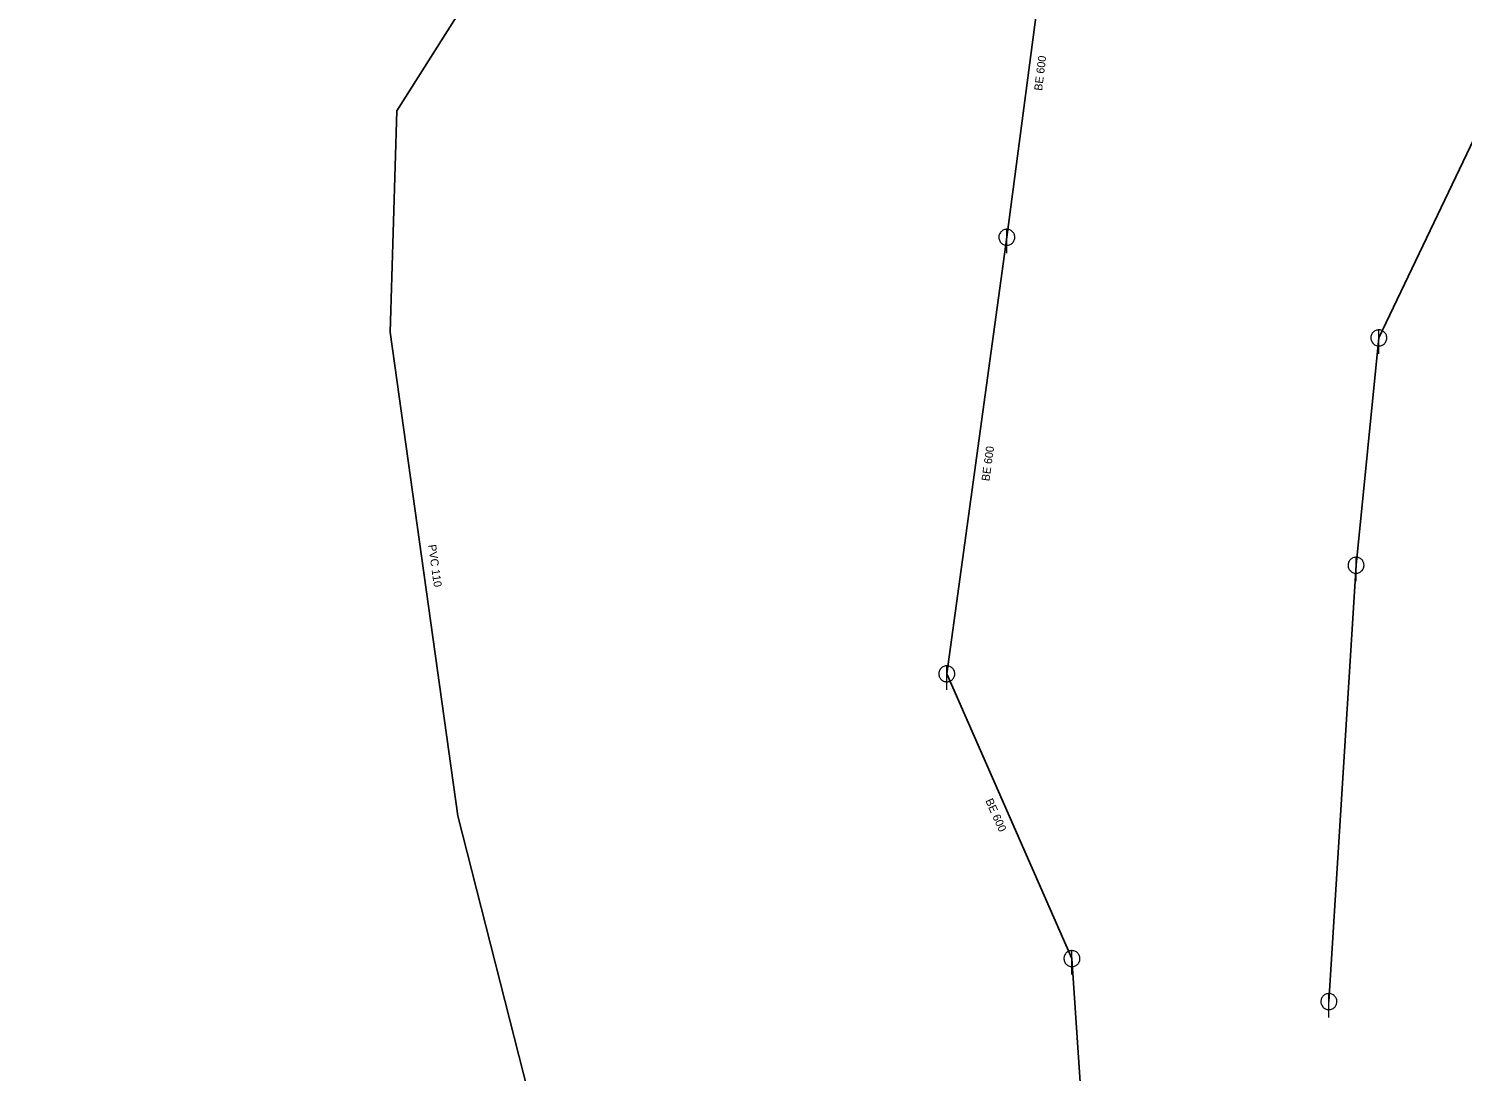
# Model space of a CAD drawing. Extents: x -659250 to -657316, y -997555 to -993684.
# Drawn here: x -658669.3 to -658490.2, y -994349.9 to -994219.6 of the extents above; entities that cross this region are included whole.
import ezdxf

# ---------------------------------------------------------------- set-up
doc = ezdxf.new("R2010")
doc.units = 0
doc.header["$LTSCALE"] = 0.4
doc.layers.add('1', color=7, linetype='Continuous')
for name, color, linetype, lineweight in [('14', 7, 'Continuous', 25), ('17', 7, 'Continuous', 25), ('22', 7, 'Continuous', 13)]:
    doc.layers.add(name, color=color, linetype=linetype, lineweight=lineweight)

msp = doc.modelspace()

# ---------------------------------------------------------------- linework, layer by layer
at = {"layer": '14'}
for p, q in [((-658547.12, -994245.69), (-658541.489, -994202.69)), ((-658506.89, -994341.18), (-658503.5, -994286.66))]:
    msp.add_line(p, q, dxfattribs=at)
for points in [[(-658503.5, -994286.66), (-658500.649, -994258.26), (-658488.28, -994232.379)], [(-658538.989, -994335.809), (-658554.62, -994300.23), (-658547.12, -994245.69)], [(-658665.989, -994692.25), (-658669.32, -994646.26), (-658665.8, -994630.84), (-658645.039, -994594.649), (-658628.309, -994572.48), (-658618.039, -994539.21), (-658605.98, -994522.41), (-658563.96, -994494.52), (-658544.98, -994467.27), (-658532.93, -994425.92), (-658538.989, -994335.809)]]:
    msp.add_lwpolyline(points, dxfattribs=at)
at = {"layer": '17'}
msp.add_lwpolyline([(-658613.3, -994213.989), (-658613.524, -994214.403), (-658623.307, -994229.89), (-658624.14, -994257.537), (-658615.692, -994317.956), (-658606.899, -994352.517), (-658587.086, -994395.585), (-658588.159, -994408.494), (-658589.278, -994412.67), (-658589.404, -994413.139), (-658612.337, -994451.366), (-658612.825, -994451.789), (-658615.8, -994453.061)], dxfattribs=at)
at = {"layer": '22'}
for p, q in [((-658547.12, -994247.69), (-658547.119, -994244.69)), ((-658500.649, -994260.26), (-658500.648, -994257.26)), ((-658503.5, -994288.66), (-658503.499, -994285.66)), ((-658554.62, -994302.23), (-658554.619, -994299.23)), ((-658538.989, -994337.809), (-658538.988, -994334.809)), ((-658506.89, -994343.18), (-658506.889, -994340.18))]:
    msp.add_line(p, q, dxfattribs=at)
for points in [[(-658546.12, -994245.69), (-658546.125, -994245.581), (-658546.143, -994245.473), (-658546.173, -994245.367), (-658546.213, -994245.266), (-658546.265, -994245.169), (-658546.327, -994245.079), (-658546.399, -994244.996), (-658546.479, -994244.922), (-658546.567, -994244.856), (-658546.661, -994244.801), (-658546.761, -994244.756), (-658546.866, -994244.723), (-658546.973, -994244.701), (-658547.082, -994244.691), (-658547.192, -994244.693), (-658547.3, -994244.707), (-658547.407, -994244.732), (-658547.51, -994244.769), (-658547.608, -994244.818), (-658547.7, -994244.876), (-658547.786, -994244.945), (-658547.863, -994245.022), (-658547.932, -994245.108), (-658547.991, -994245.2), (-658548.039, -994245.298), (-658548.076, -994245.401), (-658548.102, -994245.508), (-658548.116, -994245.616), (-658548.119, -994245.726), (-658548.109, -994245.835), (-658548.088, -994245.942), (-658548.054, -994246.046), (-658548.01, -994246.146), (-658547.955, -994246.241), (-658547.889, -994246.329), (-658547.815, -994246.409), (-658547.732, -994246.481), (-658547.642, -994246.543), (-658547.546, -994246.595), (-658547.444, -994246.636), (-658547.339, -994246.666), (-658547.231, -994246.684), (-658547.121, -994246.69), (-658547.012, -994246.684), (-658546.904, -994246.666), (-658546.799, -994246.637), (-658546.697, -994246.596), (-658546.6, -994246.544), (-658546.51, -994246.482), (-658546.427, -994246.411), (-658546.352, -994246.331), (-658546.287, -994246.243), (-658546.231, -994246.149), (-658546.187, -994246.049), (-658546.153, -994245.945), (-658546.131, -994245.837), (-658546.121, -994245.728)], [(-658499.649, -994258.26), (-658499.654, -994258.151), (-658499.672, -994258.043), (-658499.702, -994257.937), (-658499.742, -994257.836), (-658499.794, -994257.739), (-658499.856, -994257.649), (-658499.928, -994257.566), (-658500.008, -994257.492), (-658500.096, -994257.426), (-658500.19, -994257.371), (-658500.29, -994257.326), (-658500.395, -994257.293), (-658500.502, -994257.271), (-658500.611, -994257.261), (-658500.721, -994257.263), (-658500.829, -994257.277), (-658500.936, -994257.302), (-658501.039, -994257.339), (-658501.137, -994257.388), (-658501.229, -994257.446), (-658501.315, -994257.515), (-658501.392, -994257.592), (-658501.461, -994257.678), (-658501.52, -994257.77), (-658501.568, -994257.868), (-658501.605, -994257.971), (-658501.631, -994258.078), (-658501.645, -994258.186), (-658501.648, -994258.296), (-658501.638, -994258.405), (-658501.617, -994258.512), (-658501.583, -994258.616), (-658501.539, -994258.716), (-658501.484, -994258.811), (-658501.418, -994258.899), (-658501.344, -994258.979), (-658501.261, -994259.051), (-658501.171, -994259.113), (-658501.075, -994259.165), (-658500.973, -994259.206), (-658500.868, -994259.236), (-658500.76, -994259.254), (-658500.65, -994259.26), (-658500.541, -994259.254), (-658500.433, -994259.236), (-658500.328, -994259.207), (-658500.226, -994259.166), (-658500.129, -994259.114), (-658500.039, -994259.052), (-658499.956, -994258.981), (-658499.881, -994258.901), (-658499.816, -994258.813), (-658499.76, -994258.719), (-658499.716, -994258.619), (-658499.682, -994258.515), (-658499.66, -994258.407), (-658499.65, -994258.298)], [(-658502.5, -994286.66), (-658502.505, -994286.551), (-658502.523, -994286.443), (-658502.553, -994286.337), (-658502.593, -994286.236), (-658502.645, -994286.139), (-658502.707, -994286.049), (-658502.779, -994285.966), (-658502.859, -994285.892), (-658502.947, -994285.826), (-658503.041, -994285.771), (-658503.141, -994285.726), (-658503.246, -994285.693), (-658503.353, -994285.671), (-658503.462, -994285.661), (-658503.572, -994285.663), (-658503.68, -994285.677), (-658503.787, -994285.702), (-658503.89, -994285.739), (-658503.988, -994285.788), (-658504.08, -994285.846), (-658504.166, -994285.915), (-658504.243, -994285.992), (-658504.312, -994286.078), (-658504.371, -994286.17), (-658504.419, -994286.268), (-658504.456, -994286.371), (-658504.482, -994286.478), (-658504.496, -994286.586), (-658504.499, -994286.696), (-658504.489, -994286.805), (-658504.468, -994286.912), (-658504.434, -994287.016), (-658504.39, -994287.116), (-658504.335, -994287.211), (-658504.269, -994287.299), (-658504.195, -994287.379), (-658504.112, -994287.451), (-658504.022, -994287.513), (-658503.926, -994287.565), (-658503.824, -994287.606), (-658503.719, -994287.636), (-658503.611, -994287.654), (-658503.501, -994287.66), (-658503.392, -994287.654), (-658503.284, -994287.636), (-658503.179, -994287.607), (-658503.077, -994287.566), (-658502.98, -994287.514), (-658502.89, -994287.452), (-658502.807, -994287.381), (-658502.732, -994287.301), (-658502.667, -994287.213), (-658502.611, -994287.119), (-658502.567, -994287.019), (-658502.533, -994286.915), (-658502.511, -994286.807), (-658502.501, -994286.698)], [(-658553.62, -994300.23), (-658553.625, -994300.121), (-658553.643, -994300.013), (-658553.673, -994299.907), (-658553.713, -994299.806), (-658553.765, -994299.709), (-658553.827, -994299.619), (-658553.899, -994299.536), (-658553.979, -994299.462), (-658554.067, -994299.396), (-658554.161, -994299.341), (-658554.261, -994299.296), (-658554.366, -994299.263), (-658554.473, -994299.241), (-658554.582, -994299.231), (-658554.692, -994299.233), (-658554.8, -994299.247), (-658554.907, -994299.272), (-658555.01, -994299.309), (-658555.108, -994299.358), (-658555.2, -994299.416), (-658555.286, -994299.485), (-658555.363, -994299.562), (-658555.432, -994299.648), (-658555.491, -994299.74), (-658555.539, -994299.838), (-658555.576, -994299.941), (-658555.602, -994300.048), (-658555.616, -994300.156), (-658555.619, -994300.266), (-658555.609, -994300.375), (-658555.588, -994300.482), (-658555.554, -994300.586), (-658555.51, -994300.686), (-658555.455, -994300.781), (-658555.389, -994300.869), (-658555.315, -994300.949), (-658555.232, -994301.021), (-658555.142, -994301.083), (-658555.046, -994301.135), (-658554.944, -994301.176), (-658554.839, -994301.206), (-658554.731, -994301.224), (-658554.621, -994301.23), (-658554.512, -994301.224), (-658554.404, -994301.206), (-658554.299, -994301.177), (-658554.197, -994301.136), (-658554.1, -994301.084), (-658554.01, -994301.022), (-658553.927, -994300.951), (-658553.852, -994300.871), (-658553.787, -994300.783), (-658553.731, -994300.689), (-658553.687, -994300.589), (-658553.653, -994300.485), (-658553.631, -994300.377), (-658553.621, -994300.268)], [(-658537.989, -994335.809), (-658537.994, -994335.7), (-658538.012, -994335.592), (-658538.042, -994335.486), (-658538.082, -994335.385), (-658538.134, -994335.288), (-658538.196, -994335.198), (-658538.268, -994335.115), (-658538.348, -994335.041), (-658538.436, -994334.975), (-658538.53, -994334.92), (-658538.63, -994334.875), (-658538.735, -994334.842), (-658538.842, -994334.82), (-658538.951, -994334.81), (-658539.061, -994334.812), (-658539.169, -994334.826), (-658539.276, -994334.851), (-658539.379, -994334.888), (-658539.477, -994334.937), (-658539.569, -994334.995), (-658539.655, -994335.064), (-658539.732, -994335.141), (-658539.801, -994335.227), (-658539.86, -994335.319), (-658539.908, -994335.417), (-658539.945, -994335.52), (-658539.971, -994335.627), (-658539.985, -994335.735), (-658539.988, -994335.845), (-658539.978, -994335.954), (-658539.957, -994336.061), (-658539.923, -994336.165), (-658539.879, -994336.265), (-658539.824, -994336.36), (-658539.758, -994336.448), (-658539.684, -994336.528), (-658539.601, -994336.6), (-658539.511, -994336.662), (-658539.415, -994336.714), (-658539.313, -994336.755), (-658539.208, -994336.785), (-658539.1, -994336.803), (-658538.99, -994336.809), (-658538.881, -994336.803), (-658538.773, -994336.785), (-658538.668, -994336.756), (-658538.566, -994336.715), (-658538.469, -994336.663), (-658538.379, -994336.601), (-658538.296, -994336.53), (-658538.221, -994336.45), (-658538.156, -994336.362), (-658538.1, -994336.268), (-658538.056, -994336.168), (-658538.022, -994336.064), (-658538, -994335.956), (-658537.99, -994335.847)], [(-658505.89, -994341.18), (-658505.895, -994341.071), (-658505.913, -994340.963), (-658505.943, -994340.857), (-658505.983, -994340.756), (-658506.035, -994340.659), (-658506.097, -994340.569), (-658506.169, -994340.486), (-658506.249, -994340.412), (-658506.337, -994340.346), (-658506.431, -994340.291), (-658506.531, -994340.246), (-658506.636, -994340.213), (-658506.743, -994340.191), (-658506.852, -994340.181), (-658506.962, -994340.183), (-658507.07, -994340.197), (-658507.177, -994340.222), (-658507.28, -994340.259), (-658507.378, -994340.308), (-658507.47, -994340.366), (-658507.556, -994340.435), (-658507.633, -994340.512), (-658507.702, -994340.598), (-658507.761, -994340.69), (-658507.809, -994340.788), (-658507.846, -994340.891), (-658507.872, -994340.998), (-658507.886, -994341.106), (-658507.889, -994341.216), (-658507.879, -994341.325), (-658507.858, -994341.432), (-658507.824, -994341.536), (-658507.78, -994341.636), (-658507.725, -994341.731), (-658507.659, -994341.819), (-658507.585, -994341.899), (-658507.502, -994341.971), (-658507.412, -994342.033), (-658507.316, -994342.085), (-658507.214, -994342.126), (-658507.109, -994342.156), (-658507.001, -994342.174), (-658506.891, -994342.18), (-658506.782, -994342.174), (-658506.674, -994342.156), (-658506.569, -994342.127), (-658506.467, -994342.086), (-658506.37, -994342.034), (-658506.28, -994341.972), (-658506.197, -994341.901), (-658506.122, -994341.821), (-658506.057, -994341.733), (-658506.001, -994341.639), (-658505.957, -994341.539), (-658505.923, -994341.435), (-658505.901, -994341.327), (-658505.891, -994341.218)]]:
    msp.add_lwpolyline(points, close=True, dxfattribs=at)

# ---------------------------------------------------------------- texts
at = {"layer": '1'}
for s, rotation, p in [('BE 600', 83, (-658542.725, -994227.421)), ('BE 600', 82, (-658549.311, -994276.202)), ('PVC 110 ', 278, (-658619.424, -994284.142)), ('BE 600', 294, (-658549.828, -994316.071))]:
    msp.add_text(s, height=1, rotation=rotation, dxfattribs=at).set_placement(p)

doc.saveas('drawing.dxf')
